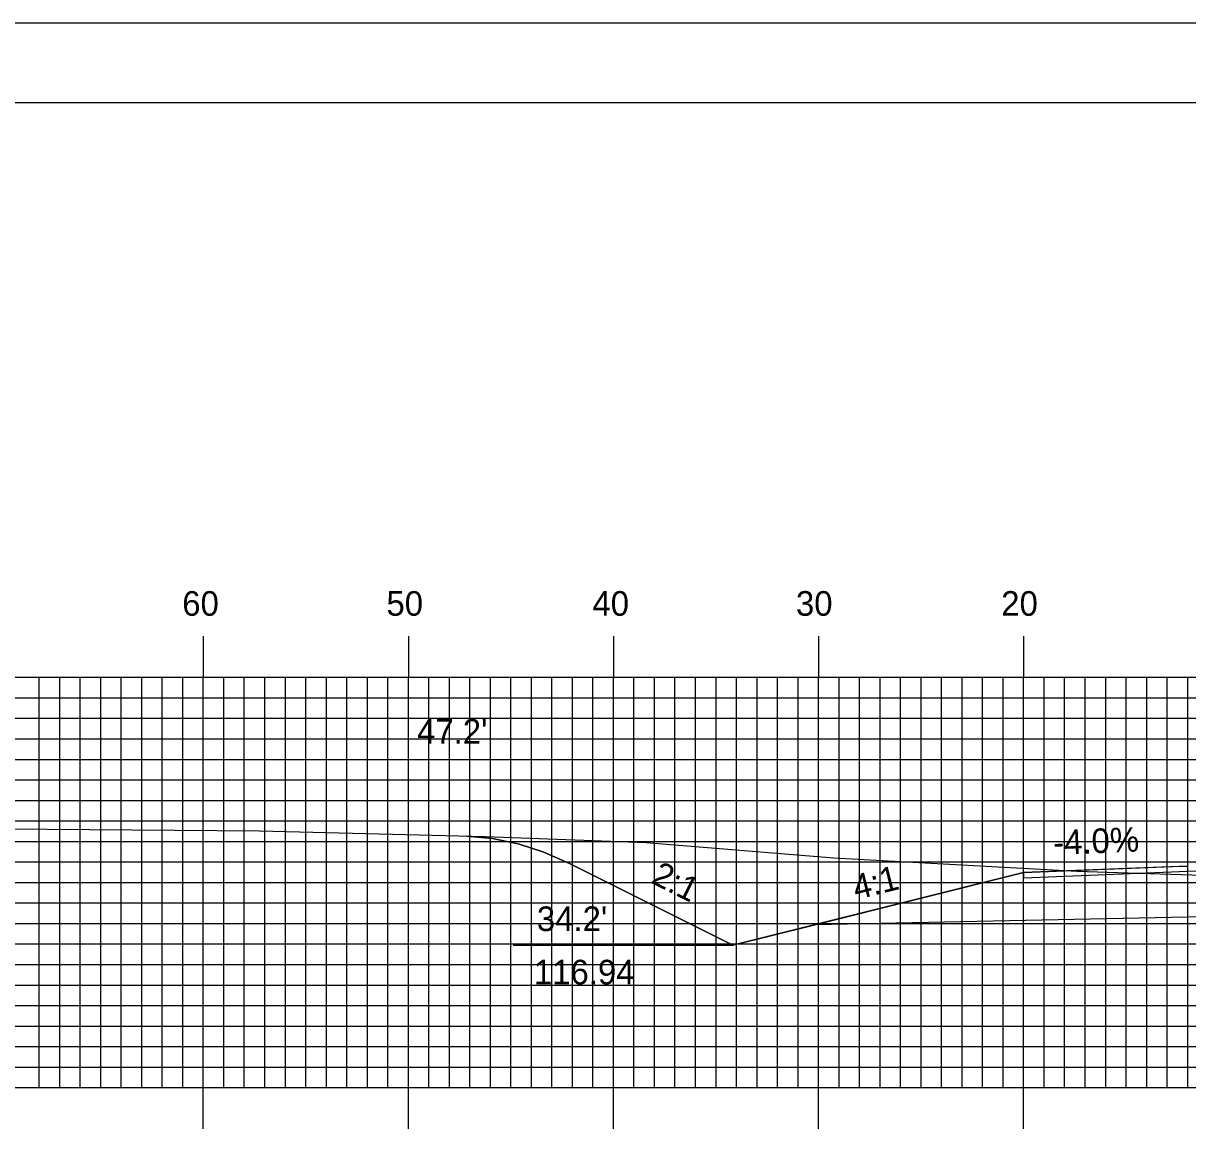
# Model space of a CAD drawing. Extents: x 1770842 to 1771185, y 442591 to 442811.
# Drawn here: x 1770938.8 to 1770995.6, y 442756.2 to 442810.5 of the extents above; entities that cross this region are included whole.
import ezdxf

# ---------------------------------------------------------------- set-up
doc = ezdxf.new("R2010")
doc.units = 0
for name, color, linetype in [('ANNOTATION', 7, 'Continuous'), ('BORDER', 7, 'Continuous'), ('D_Roadway_Centerline', 7, 'Continuous'), ('D_Roadway_Edge_Shoulder', 7, 'Continuous'), ('D_Roadway_SlopeLines', 7, 'Continuous'), ('D_Roadway_SubGrade', 7, 'Continuous'), ('D_Text_Standard', 7, 'Continuous'), ('H_V ANNOTATION', 7, 'Continuous'), ('MAJOR', 7, 'Continuous'), ('MINOR', 7, 'Continuous'), ('PDRAIN', 7, 'Continuous'), ('PLOT BOUNDARY', 7, 'Continuous'), ('S_Roadway_Centerline', 7, 'Continuous')]:
    doc.layers.add(name, color=color, linetype=linetype)

msp = doc.modelspace()

# ---------------------------------------------------------------- linework, layer by layer
at = {"layer": 'BORDER'}
msp.add_lwpolyline([(1770857.954, 442596.665), (1771177.954, 442596.665), (1771177.954, 442806.665), (1770857.954, 442806.665)], close=True, dxfattribs=at)
at = {"layer": 'D_Roadway_Centerline'}
msp.add_lwpolyline([(1770960.405, 442770.92), (1770961.655, 442770.807), (1770962.905, 442770.547), (1770964.155, 442770.142), (1770965.405, 442769.59), (1770973.38, 442765.602), (1770977.38, 442766.602), (1770982.601, 442767.908), (1770987.553, 442769.146), (1770987.554, 442769.146), (1770995.212, 442769.453), (1770995.555, 442769.466)], dxfattribs=at)
at = {"layer": 'D_Roadway_Edge_Shoulder'}
msp.add_lwpolyline([(1770995.554, 442769.466), (1770987.554, 442769.146), (1770987.554, 442768.896), (1770995.554, 442769.216)], close=True, dxfattribs=at)
at = {"layer": 'D_Roadway_SlopeLines'}
for points in [[(1770973.38, 442765.602), (1770965.405, 442769.59), (1770964.155, 442770.142), (1770962.905, 442770.547), (1770961.655, 442770.807), (1770960.405, 442770.92)], [(1770987.554, 442769.146), (1770973.38, 442765.602)]]:
    msp.add_lwpolyline(points, dxfattribs=at)
at = {"layer": 'D_Roadway_SubGrade'}
msp.add_lwpolyline([(1770995.554, 442766.966), (1770977.38, 442766.602), (1770987.554, 442769.146), (1770987.554, 442768.896), (1770995.554, 442769.216), (1771007.554, 442769.456), (1771019.554, 442769.216), (1771027.554, 442768.896), (1771027.554, 442769.146), (1771037.729, 442766.602), (1771019.554, 442766.966), (1771007.554, 442767.206)], close=True, dxfattribs=at)
at = {"layer": 'MAJOR'}
for p, q in [((1770947.554, 442780.669), (1770947.554, 442778.665)), ((1770957.554, 442780.669), (1770957.554, 442778.665)), ((1770967.554, 442780.669), (1770967.554, 442778.665)), ((1770977.554, 442780.669), (1770977.554, 442778.665)), ((1770987.554, 442780.669), (1770987.554, 442778.665)), ((1770867.554, 442778.665), (1771147.554, 442778.665)), ((1770867.554, 442778.665), (1771147.554, 442778.665)), ((1770947.554, 442758.665), (1770947.554, 442778.665)), ((1770957.554, 442758.665), (1770957.554, 442778.665)), ((1770967.554, 442758.665), (1770967.554, 442778.665)), ((1770977.554, 442758.665), (1770977.554, 442778.665)), ((1770987.554, 442758.665), (1770987.554, 442778.665)), ((1770867.554, 442773.665), (1771147.554, 442773.665)), ((1770867.554, 442768.665), (1771147.554, 442768.665)), ((1770867.554, 442763.665), (1771147.554, 442763.665)), ((1770867.554, 442758.665), (1771147.554, 442758.665)), ((1770867.554, 442758.665), (1771147.554, 442758.665)), ((1770947.554, 442756.661), (1770947.554, 442758.665)), ((1770957.554, 442756.661), (1770957.554, 442758.665)), ((1770967.554, 442756.661), (1770967.554, 442758.665)), ((1770977.554, 442756.661), (1770977.554, 442758.665)), ((1770987.554, 442756.661), (1770987.554, 442758.665))]:
    msp.add_line(p, q, dxfattribs=at)
at = {"layer": 'MINOR'}
for p, q in [((1770939.554, 442758.665), (1770939.554, 442778.665)), ((1770940.554, 442758.665), (1770940.554, 442778.665)), ((1770941.554, 442758.665), (1770941.554, 442778.665)), ((1770942.554, 442758.665), (1770942.554, 442778.665)), ((1770943.554, 442758.665), (1770943.554, 442778.665)), ((1770944.554, 442758.665), (1770944.554, 442778.665)), ((1770945.554, 442758.665), (1770945.554, 442778.665)), ((1770946.554, 442758.665), (1770946.554, 442778.665)), ((1770948.554, 442758.665), (1770948.554, 442778.665)), ((1770949.554, 442758.665), (1770949.554, 442778.665)), ((1770950.554, 442758.665), (1770950.554, 442778.665)), ((1770951.554, 442758.665), (1770951.554, 442778.665)), ((1770952.554, 442758.665), (1770952.554, 442778.665)), ((1770953.554, 442758.665), (1770953.554, 442778.665)), ((1770954.554, 442758.665), (1770954.554, 442778.665)), ((1770955.554, 442758.665), (1770955.554, 442778.665)), ((1770956.554, 442758.665), (1770956.554, 442778.665)), ((1770958.554, 442758.665), (1770958.554, 442778.665)), ((1770959.554, 442758.665), (1770959.554, 442778.665)), ((1770960.554, 442758.665), (1770960.554, 442778.665)), ((1770961.554, 442758.665), (1770961.554, 442778.665)), ((1770962.554, 442758.665), (1770962.554, 442778.665)), ((1770963.554, 442758.665), (1770963.554, 442778.665)), ((1770964.554, 442758.665), (1770964.554, 442778.665)), ((1770965.554, 442758.665), (1770965.554, 442778.665)), ((1770966.554, 442758.665), (1770966.554, 442778.665)), ((1770968.554, 442758.665), (1770968.554, 442778.665)), ((1770969.554, 442758.665), (1770969.554, 442778.665)), ((1770970.554, 442758.665), (1770970.554, 442778.665)), ((1770971.554, 442758.665), (1770971.554, 442778.665)), ((1770972.554, 442758.665), (1770972.554, 442778.665)), ((1770973.554, 442758.665), (1770973.554, 442778.665)), ((1770974.554, 442758.665), (1770974.554, 442778.665)), ((1770975.554, 442758.665), (1770975.554, 442778.665)), ((1770976.554, 442758.665), (1770976.554, 442778.665)), ((1770978.554, 442758.665), (1770978.554, 442778.665)), ((1770979.554, 442758.665), (1770979.554, 442778.665)), ((1770980.554, 442758.665), (1770980.554, 442778.665)), ((1770981.554, 442758.665), (1770981.554, 442778.665)), ((1770982.554, 442758.665), (1770982.554, 442778.665)), ((1770983.554, 442758.665), (1770983.554, 442778.665)), ((1770984.554, 442758.665), (1770984.554, 442778.665)), ((1770985.554, 442758.665), (1770985.554, 442778.665)), ((1770986.554, 442758.665), (1770986.554, 442778.665)), ((1770988.554, 442758.665), (1770988.554, 442778.665)), ((1770989.554, 442758.665), (1770989.554, 442778.665)), ((1770990.554, 442758.665), (1770990.554, 442778.665)), ((1770991.554, 442758.665), (1770991.554, 442778.665)), ((1770992.554, 442758.665), (1770992.554, 442778.665)), ((1770993.554, 442758.665), (1770993.554, 442778.665)), ((1770994.554, 442758.665), (1770994.554, 442778.665)), ((1770995.554, 442758.665), (1770995.554, 442778.665)), ((1770867.554, 442777.665), (1771147.554, 442777.665)), ((1770867.554, 442776.665), (1771147.554, 442776.665)), ((1770867.554, 442775.665), (1771147.554, 442775.665)), ((1770867.554, 442774.665), (1771147.554, 442774.665)), ((1770867.554, 442772.665), (1771147.554, 442772.665)), ((1770867.554, 442771.665), (1771147.554, 442771.665)), ((1770867.554, 442770.665), (1771147.554, 442770.665)), ((1770867.554, 442769.665), (1771147.554, 442769.665)), ((1770867.554, 442767.665), (1771147.554, 442767.665)), ((1770867.554, 442766.665), (1771147.554, 442766.665)), ((1770867.554, 442765.665), (1771147.554, 442765.665)), ((1770867.554, 442764.665), (1771147.554, 442764.665)), ((1770867.554, 442762.665), (1771147.554, 442762.665)), ((1770867.554, 442761.665), (1771147.554, 442761.665)), ((1770867.554, 442760.665), (1771147.554, 442760.665)), ((1770867.554, 442759.665), (1771147.554, 442759.665))]:
    msp.add_line(p, q, dxfattribs=at)
at = {"layer": 'PDRAIN'}
msp.add_line((1770962.657, 442765.602), (1770973.38, 442765.602), dxfattribs=at)
at = {"layer": 'PLOT BOUNDARY'}
msp.add_lwpolyline([(1770841.768, 442590.547), (1771181.768, 442590.547), (1771181.768, 442810.547), (1770841.768, 442810.547)], close=True, dxfattribs=at)
at = {"layer": 'S_Roadway_Centerline'}
msp.add_lwpolyline([(1770933.705, 442771.306), (1770950.297, 442771.186), (1770961.307, 442770.897), (1770969.155, 442770.617), (1770978.294, 442769.864), (1770990.158, 442769.217), (1770991.625, 442769.162), (1771001.932, 442768.846), (1771009.491, 442768.674), (1771013.671, 442768.399), (1771020.095, 442768.149), (1771025.721, 442767.921), (1771030.174, 442767.727), (1771038.348, 442767.377), (1771049.281, 442767.18), (1771049.652, 442767.18), (1771069.275, 442766.891)], dxfattribs=at)

# ---------------------------------------------------------------- texts
at = {"layer": 'ANNOTATION'}
for s, rotation, p in [('-4.0%', 2.2905, (1770989.015, 442770.006)), ('2:1', 333.4329, (1770969.327, 442768.665)), ('4:1', 14.0391, (1770979.391, 442767.811))]:
    msp.add_text(s, height=1.2, rotation=rotation, dxfattribs=at).set_placement(p)
for s, p in [("34.2'", (1770963.819, 442766.294)), ('116.94', (1770963.674, 442763.694))]:
    msp.add_text(s, height=1.2, dxfattribs=at).set_placement(p)
at = {"layer": 'D_Text_Standard'}
msp.add_text("47.2'", height=1.2, dxfattribs=at).set_placement((1770957.978, 442775.429))
at = {"layer": 'H_V ANNOTATION'}
for s, p in [('60', (1770946.527, 442781.665)), ('50', (1770956.484, 442781.665)), ('40', (1770966.527, 442781.665)), ('30', (1770976.452, 442781.665)), ('20', (1770986.462, 442781.665))]:
    msp.add_text(s, height=1.2, dxfattribs=at).set_placement(p)

doc.saveas('drawing.dxf')
